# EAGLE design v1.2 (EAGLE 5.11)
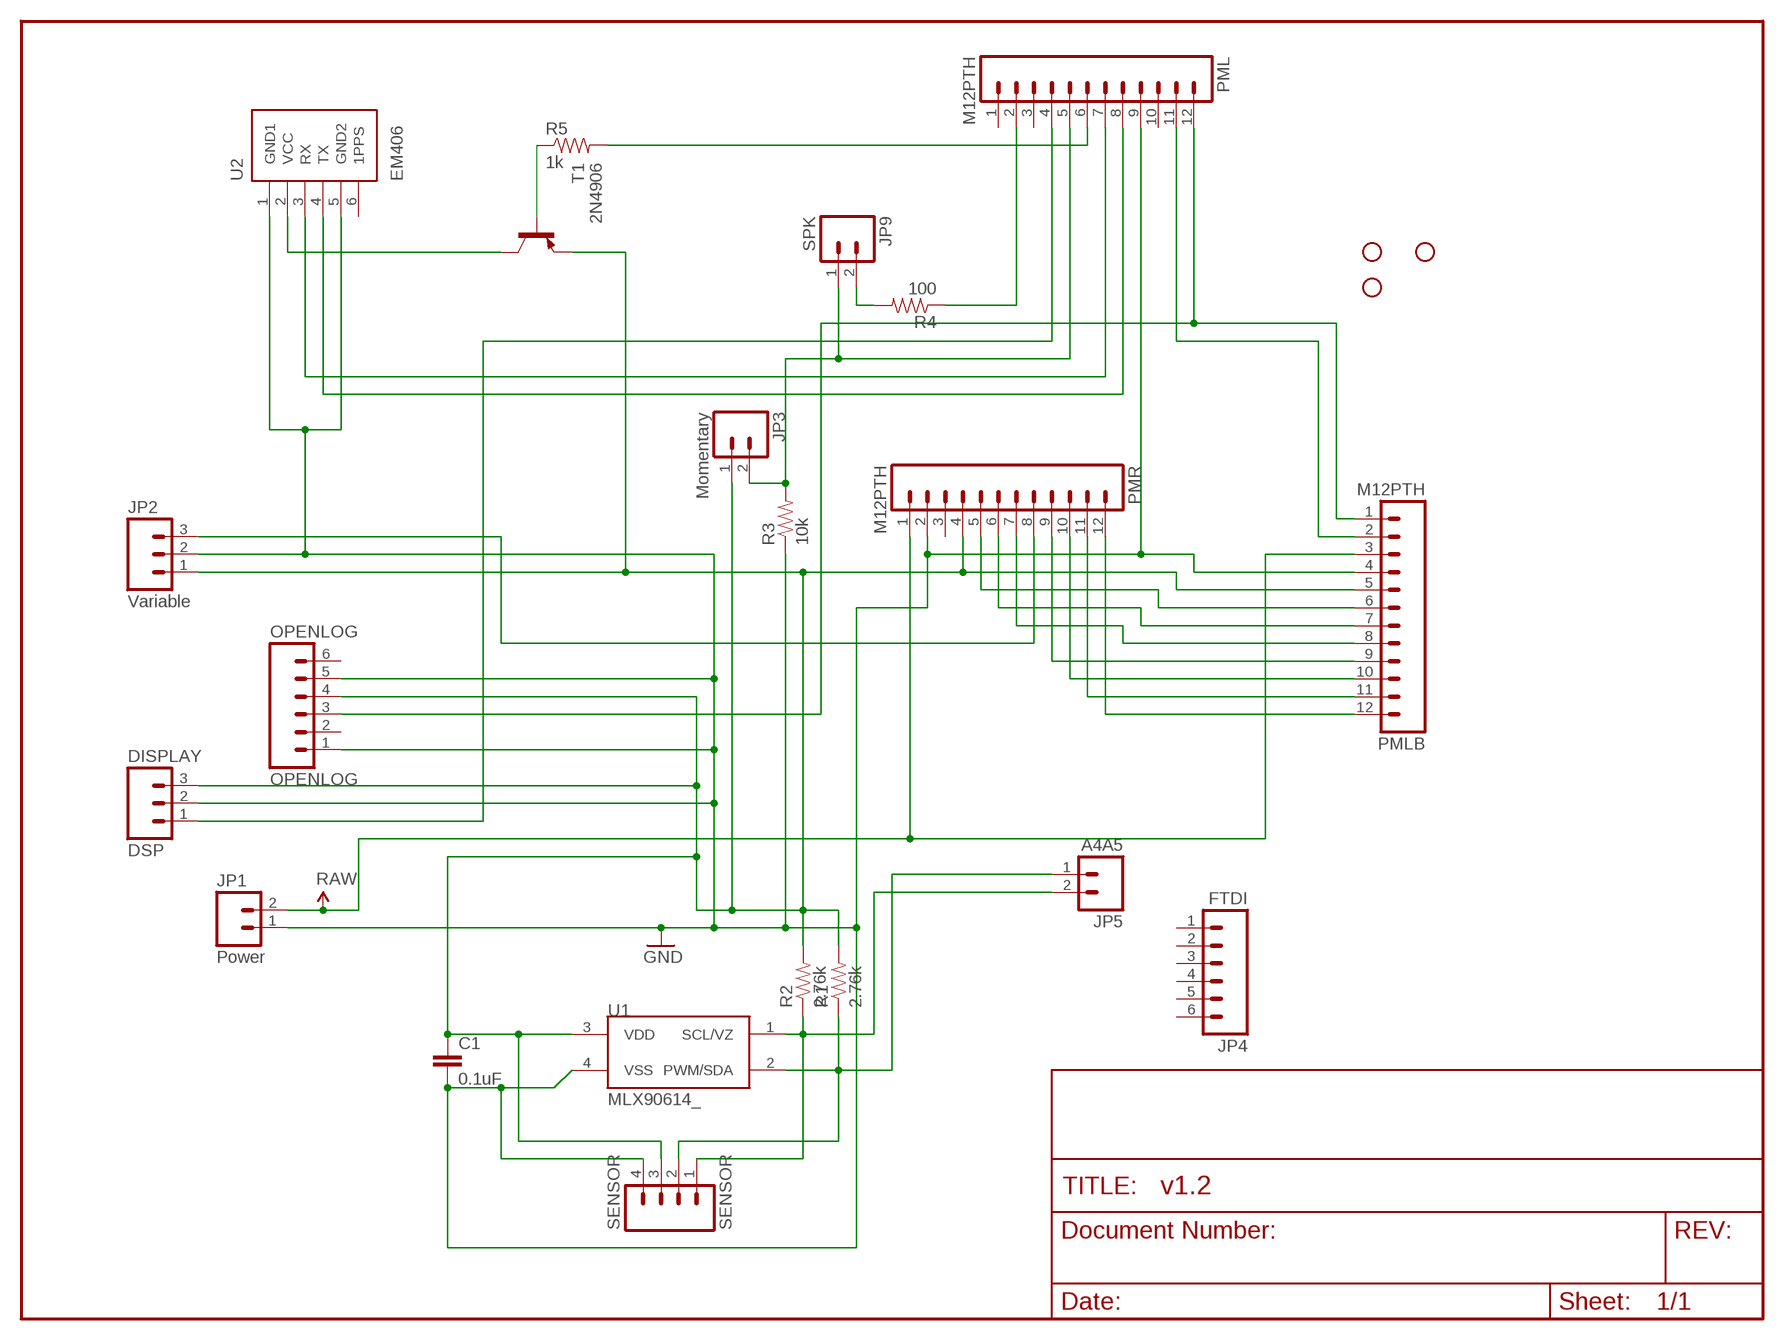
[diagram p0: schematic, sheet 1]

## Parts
2N4906  T1  2N3906-PNP-TO92-EBC  [TO92-EBC]
C1  0.1uF  CAPPTH3  [CAP-PTH-LARGE]
DISPLAY  DSP  M03SCREW_LOCK  [SCREWTERMINAL-3.5MM-3_LOCK.007S]
JP1  Power  M02JST-PTH-2  [JST-2-PTH]
JP2  Variable  M03SCREW_LOCK  [SCREWTERMINAL-3.5MM-3_LOCK.007S]
JP3  Momentary  M02JST-PTH-2  [JST-2-PTH]
JP4  FTDI  M06SIP  [1X06]
JP5  A4A5  M02PTH  [1X02]
JP6  STAND-OFFTIGHT  [STAND-OFF-TIGHT]
JP7  STAND-OFFTIGHT  [STAND-OFF-TIGHT]
JP8  STAND-OFFTIGHT  [STAND-OFF-TIGHT]
JP9  SPK  M023.5MM  [SCREWTERMINAL-3.5MM-2]
OPENLOG  OPENLOG  M06LOCK  [1X06_LOCK]
PML  M12PTH  [1X12]
PMLB  M12PTH  [1X12]
PMR  M12PTH  [1X12]
R1  2.76k  RESISTORPTH-1/4W  [AXIAL-0.4]
R2  2.76k  RESISTORPTH-1/4W  [AXIAL-0.4]
R3  10k  RESISTORPTH-1/4W  [AXIAL-0.4]
R4  100  RESISTORPTH-1/4W  [AXIAL-0.4]
R5  1k  RESISTORPTH-1/4W  [AXIAL-0.4]
SENSOR  SENSOR  M04SCREW_LOCK  [SCREWTERMINAL-3.5MM-4_LOCK]
U1  MLX90614_  [TO-39]
U2  EM406  [EM406]

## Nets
GND: C1.2 DISPLAY.2 JP1.1 JP2.2 OPENLOG.1 OPENLOG.5 PML.9 PMLB.4 PMR.2 R3.P$1 SENSOR.4 U1.4(VSS) U2.1(GND1) U2.5(GND2)
N$2: JP5.1 R1.P$1 SENSOR.2 U1.2(PWM/SDA)
N$3: JP3.2 JP9.1 PML.5 R3.P$2
N$4: DISPLAY.1 PML.4
N$5: JP2.3 PMR.8
N$6: OPENLOG.3 PML.12 PMLB.1
N$7: 2N4906.E C1.1 DISPLAY.3 JP2.1 JP3.1 OPENLOG.4 PMLB.5 PMR.4 R1.P$2 R2.P$2 SENSOR.3 U1.3(VDD)
N$8: PML.11 PMLB.2
N$9: PMLB.12 PMR.12
N$10: PMLB.11 PMR.11
N$11: PMLB.10 PMR.10
N$12: PMLB.9 PMR.9
N$13: PMLB.8 PMR.7
N$14: PMLB.7 PMR.6
N$15: PMLB.6 PMR.5
N$16: JP9.2 R4.P$2
N$17: PML.2 R4.P$1
N$18: 2N4906.B R5.P$1
N$19: 2N4906.C U2.2(VCC)
N$20: PML.8 U2.4(TX)
N$21: PML.7 U2.3(RX)
N$22: PML.6 R5.P$2
SENSOR: JP5.2 R2.P$1 SENSOR.1 U1.1(SCL/VZ)
VCC: JP1.2 PMLB.3 PMR.1 ; supply symbol labelled RAW
Unconnected: JP4.1 JP4.2 JP4.3 JP4.4 JP4.5 JP4.6 OPENLOG.2 OPENLOG.6 PML.1 PML.3 PML.10 PMR.3 U2.6(1PPS)

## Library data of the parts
2N4906 = transistor-neu-to92:*-PNP-: PNP Transistror
C1 = SparkFun:CAP: Capacitor
DISPLAY JP2 = SparkFun:M03: Header 3 Standard 3-pin 0.1" header. Use with straight break away headers (SKU : PRT-00116), right angle break away headers (PRT-00553), swiss pins (PRT-00743), machine pins (PRT-00117), and female headers (PRT-00115). Molex polarized connector foot print use with SKU : PRT-08232 with associated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
JP1 JP3 JP5 JP9 = SparkFun:M02: Header 2
JP4 OPENLOG = SparkFun:M06: Header 6 Standard 6-pin 0.1" header. Use with straight break away headers (SKU : PRT-00116), right angle break away headers (PRT-00553), swiss pins (PRT-00743), machine pins (PRT-00117), and female headers (PRT-00115). Molex polarized connector foot print use with SKU : PRT-08094 with associated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
JP6-JP8 = SparkFun:STAND-OFF: Stand Off
PML PMLB PMR = SparkFun:M12: Header 12 Standard 12-pin 0.1" header. Use with straight break away headers (SKU : PRT-00116), right angle break away headers (PRT-00553), swiss pins (PRT-00743), machine pins (PRT-00117), and female headers (PRT-00115).
R1-R5 = SparkFun:RESISTOR: Resistor
SENSOR = SparkFun:M04: Header 4 Standard 4-pin 0.1" header. Use with straight break away headers (SKU : PRT-00116), right angle break away headers (PRT-00553), swiss pins (PRT-00743), machine pins (PRT-00117), and female headers (PRT-00115). Molex polarized connector foot print use with SKU : PRT-08231 with associated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
U1 = SparkFun:MLX90614: Melexis IR Thermometer
U2 = SparkFun:EM406: EM406 Connector Proven layout and schematic for EM406 connector. Spark Fun Electronics SKU : GPS-00579

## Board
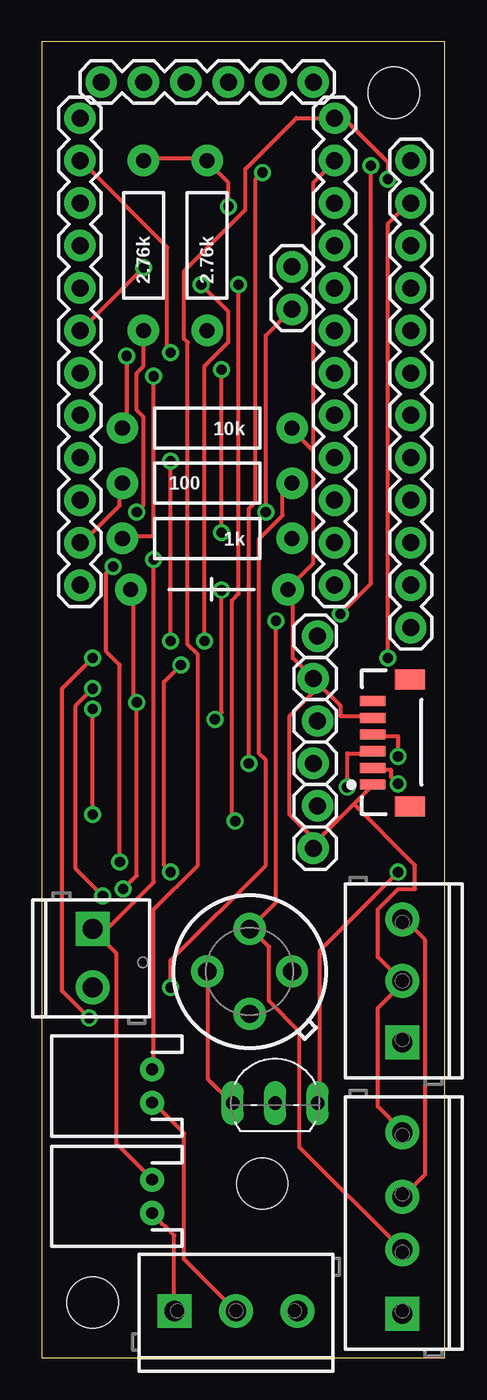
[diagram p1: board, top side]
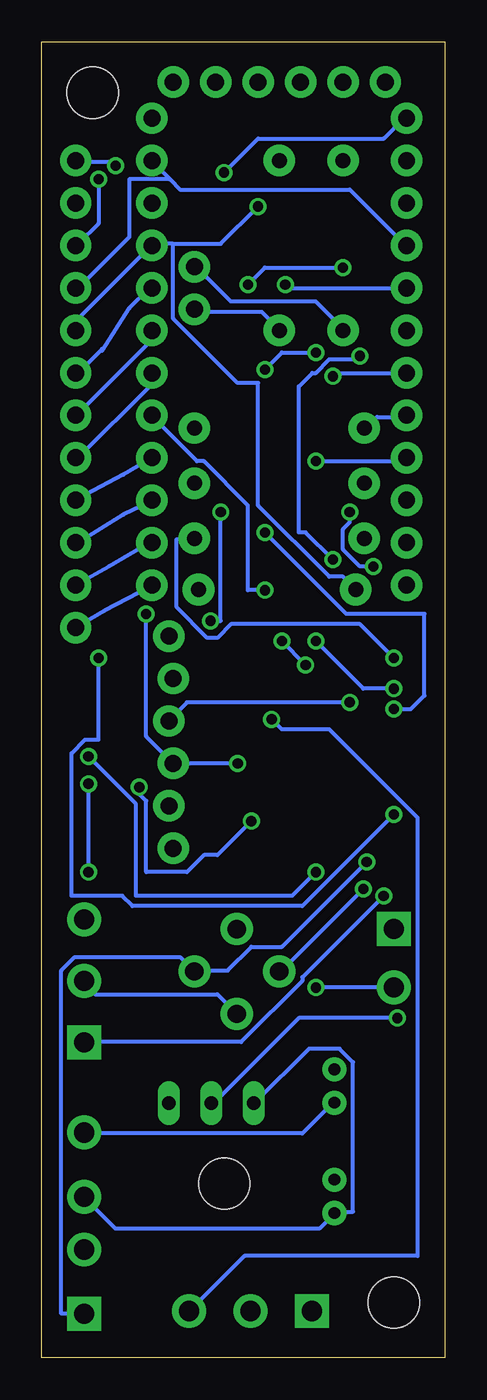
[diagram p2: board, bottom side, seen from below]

Size 24.13 x 78.74 mm. Coordinates in mm from the lower left corner, seen from the top.
Outline: 0,0 24.13,0 24.13,78.74 0,78.74 0,0
Copper layers (1*16): Top 0.035mm / dielectric 1.5mm / Bottom 0.035mm
Design rules "default": minimum track width 10mil, minimum drill 24mil, track to track 8mil, track to pad 8mil, pad to pad 8mil, via to via 8mil, smd to smd 8mil, copper to edge 40mil, drill to drill 8mil, minimum pad ring 10mil, minimum via ring 8mil, stop-mask expansion 4mil, vias tented up to drill 0mil, thermal gap 10mil

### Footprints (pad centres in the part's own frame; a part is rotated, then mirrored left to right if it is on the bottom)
TO92-EBC = drill 0.813 long: B 0,-1.27; C 2.54,-1.27; E -2.54,-1.27
CAP-PTH-LARGE = drill 0.9 pad 1.905 round: 1 -4.826,0; 2 4.572,0
SCREWTERMINAL-3.5MM-3_LOCK.007S = drill 1.2 pad 2.032 square: 1 -0.178,0 | drill 1.2 pad 2.032 round: 2 3.5,0; 3 7.178,0
JST-2-PTH = drill 0.7 pad 1.448 round: 1 -1,0; 2 1,0
1X06 = drill 1.016 pad 1.88 round: 1 0,0; 2 2.54,0; 3 5.08,0; 4 7.62,0; 5 10.16,0; 6 12.7,0
1X02 = drill 1.016 pad 1.88 round: 1 0,0; 2 2.54,0
STAND-OFF-TIGHT = hole 3.048: 0,0
SCREWTERMINAL-3.5MM-2 = drill 1.2 pad 2.032 square: 1 0,0 | drill 1.2 pad 2.032 round: 2 3.5,0
1X06_LOCK = drill 1.016 pad 1.88 round: 1 0,0; 2 2.54,-0.254; 3 5.08,0; 4 7.62,-0.254; 5 10.16,0; 6 12.7,-0.254
1X12 = drill 1.016 pad 1.88 round: 1 0,0; 2 2.54,0; 3 5.08,0; 4 7.62,0; 5 10.16,0; 6 12.7,0; 7 15.24,0; 8 17.78,0; 9 20.32,0; 10 22.86,0; 11 25.4,0; 12 27.94,0
AXIAL-0.4 = drill 0.9 pad 1.88 round: P$1 -5.08,0; P$2 5.08,0
SCREWTERMINAL-3.5MM-4_LOCK = drill 1.2 pad 2.032 square: 1 -0.178,0 | drill 1.2 pad 2.032 round: 2 3.678,0; 3 6.822,0; 4 10.678,0
TO-39 = drill 1.1 pad 1.93 round: 1 2.54,0; 2 0,2.54; 3 -2.54,0; 4 0,-2.54
EM406 = smd 0.6 x 1.55: 1 0,0; 2 1,0; 3 2,0; 4 3,0; 5 4,0; 6 5,0 | smd 1.2 x 1.8: P$1 -1.3,-2.225; P$2 6.3,-2.225

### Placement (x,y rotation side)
2N4906  13.97,16.51 0 top
C1  10.16,45.97 0 top
DISPLAY  21.59,19.05 90 top
JP1  6.6,16.26 90 top
JP2  8.13,2.79 0 top
JP3  6.6,9.65 90 top
JP4  16.26,76.33 180 top
JP5  14.99,62.74 90 top
JP6  3.05,3.3 0 top
JP7  21.08,75.69 0 top
JP8  13.21,10.41 0 top
JP9  3.05,25.65 270 top
OPENLOG  16.26,30.48 90 top
PML  2.29,46.23 90 top
PMLB  22.1,71.63 270 top
PMR  17.53,74.17 270 top
R1  9.91,66.55 90 top
R2  6.1,66.55 90 top
R3  9.91,55.63 180 top
R4  9.91,52.32 0 top
R5  9.91,49.02 180 top
SENSOR  21.59,2.79 90 top
U1  12.45,23.11 0 top
U2  19.81,34.29 90 top

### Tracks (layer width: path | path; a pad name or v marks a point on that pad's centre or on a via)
GND
  Top 0.254: JP2.2 11.58,2.85 8.53,5.89 8.53,13.41 6.71,15.24 JP1.1 | SENSOR.4 21.54,13.61 20.12,15.04 20.12,20.93 21.54,22.35 DISPLAY.2 21.54,22.55 20.12,23.98 20.12,26.82 21.34,28.04 22.35,28.04 22.35,29.46 18.69,33.12 | 16.46,30.89 16.26,30.68 OPENLOG.1 16.46,30.89 | 18.69,33.12 16.46,30.89 | 18.69,33.12 19.71,34.14 U2.1 | 16.66,40.23 17.88,39.01 17.88,38.41 19.71,38.41 U2.5 | 16.26,54.25 15.04,55.47 R3.P$1 | 16.26,54.25 16.26,47.55 15.04,46.33 | 15.04,46.33 14.83,46.13 C1.2 15.04,46.33 | 15.04,46.33 15.04,41.86 OPENLOG.5 16.66,40.23 | 16.46,30.89 14.83,32.51 14.83,38.41 16.66,40.23 | 16.26,54.25 16.26,70.31 17.48,71.53 PMR.2
  Bottom 0.254: U1.4 13.61,21.74 20.93,21.74 21.54,22.35 DISPLAY.2 | JP1.1 6.71,15.24 8.53,13.41 21.54,13.41 SENSOR.4 | 16.46,70.51 17.48,71.53 PMR.2 | 16.46,70.51 15.85,69.9 5.69,69.9 2.44,66.65 PML.9 | 16.46,70.51 18.9,70.51 18.9,67.06 21.95,64.01 PMLB.4
N$2  (via drill 0.61)
  Top 0.254: SENSOR.2 21.54,6.5 15.44,12.6 15.44,19.51 13.61,21.34 13.61,24.59 12.6,25.6 U1.2 14.02,27.23 v14.02,44.09 | v13.41,50.6 13.41,61.16 JP5.1
  Bottom 0.254: R1.P$1 9.96,61.57 10.97,62.59 14.83,62.59 JP5.1 | v13.41,50.6 13.41,44.09 v14.02,44.09
N$3  (via drill 0.61)
  Top 0.254: 3.45,25.2 3.05,25.6 JP9.1 3.45,25.2 | 3.45,25.2 4.47,24.18 4.47,12.8 6.5,10.77 JP3.2 | v5.08,59.94 5.08,55.88 R3.P$2 | v6.71,47.75 6.71,28.45 3.45,25.2
  Bottom 0.254: R3.P$2 4.67,55.68 4.06,56.29 2.44,56.29 PML.5 | v5.08,59.94 5.28,59.74 6.91,59.74 7.72,58.93 7.92,58.93 8.74,58.12 8.74,49.38 8.33,49.38 v6.71,47.75
N$4  (via drill 0.61)
  Top 0.254: v7.72,42.88 v7.72,53.65 | v3.05,40.03 2.03,39.01 2.03,29.26 v3.66,27.64
  Bottom 0.254: v7.72,53.65 2.64,53.65 2.44,53.85 PML.4 | v7.72,42.88 4.88,40.03 v3.05,40.03 | v3.66,27.64 8.53,22.76 8.53,22.55 12.19,18.9 21.54,18.9 DISPLAY.1
N$5  (via drill 0.61)
  Top 0.254: v10.77,45.92 10.77,38.61 v10.36,38.2
  Bottom 0.254: v10.77,45.92 11.79,45.92 11.79,51 14.43,53.65 14.83,53.65 17.48,56.29 PMR.8 | v10.36,38.2 9.75,37.59 6.91,37.59 1.63,32.31 1.63,6.1 11.99,6.1 15.24,2.85 JP2.3
N$6  (via drill 0.61)
  Top 0.254: v17.88,44.5 19.71,46.33 v19.71,71.32 | v13.21,70.92 12.8,70.51 12.8,51.21 12.39,50.8 v12.39,35.56
  Bottom 0.254: v17.88,44.5 17.88,37.19 OPENLOG.3 v12.39,35.56 | v19.71,71.32 19.91,71.53 21.95,71.53 PMLB.1 | v13.21,70.92 11.18,72.95 3.66,72.95 2.44,74.17 PML.12
N$7  (via drill 0.61)
  Top 0.254: 2N4906.E 11.38,15.24 9.96,16.66 9.96,22.96 U1.3 | JP3.1 6.71,8.53 7.92,7.32 7.92,2.85 JP2.1 | DISPLAY.3 21.74,26.21 22.96,24.99 22.96,10.97 21.74,9.75 SENSOR.3 | C1.1 5.49,45.92 5.49,39.42 v5.69,39.22 5.69,28.85 v4.88,28.04 | R2.P$2 6.1,71.73 9.75,71.73 R1.P$2 9.96,71.53 11.18,70.31 v11.18,68.89
  Bottom 0.254: SENSOR.3 21.54,9.55 19.71,7.72 7.52,7.72 6.71,8.53 JP3.1 6.5,8.74 5.49,8.74 5.49,17.68 6.3,18.49 8.13,18.49 11.38,15.24 2N4906.E | v5.69,39.22 15.44,39.22 16.46,38.2 OPENLOG.4 | PMLB.5 21.95,61.57 21.95,62.18 17.68,66.45 PMR.4 17.48,66.65 16.26,66.65 | v11.18,68.89 13.41,66.65 16.26,66.65 | 16.26,66.65 16.26,62.18 12.39,58.32 11.18,58.32 11.18,51 6.91,46.74 6.1,46.74 C1.1 | v4.88,28.04 9.75,23.16 U1.3
N$8  (via drill 0.61)
  Top 0.254: v20.73,41.86 20.73,67.87 21.95,69.09 PMLB.2 | v3.05,32.51 v3.05,38.81 | v10.77,49.38 v10.77,59.13 | v7.72,60.15 7.52,60.35 7.52,66.45 2.44,71.53 PML.11
  Bottom 0.254: v20.73,41.86 20.73,36.98 21.54,36.98 22.35,36.17 22.35,27.64 19.3,27.64 18.69,27.03 8.53,27.03 v3.05,32.51 | v3.05,38.81 2.03,38.81 1.22,39.62 1.22,44.5 5.89,44.5 v10.77,49.38 | v10.77,59.13 9.75,60.15 v7.72,60.15
N$9
  Bottom 0.254: PMR.12 17.68,46.13 20.37,44.7 PMLB.12
N$10
  Bottom 0.254: PMR.11 17.68,48.77 20.12,47.35 21.95,46.33 PMLB.11
N$11
  Bottom 0.254: PMLB.10 21.95,48.77 19.25,50.44 17.68,51.21 PMR.10
N$12
  Bottom 0.254: PMLB.9 21.95,51.41 19.25,52.83 PMR.9
N$13
  Bottom 0.254: PMLB.8 21.95,53.85 17.68,58.12 17.68,58.93 PMR.7
N$14
  Bottom 0.254: PMLB.7 21.95,56.49 17.68,60.76 17.68,61.37 PMR.6
N$15
  Bottom 0.254: PMLB.6 21.95,58.93 20.52,60.35 20.52,60.25 18.9,62.79 17.68,64.01 PMR.5
N$16  (via drill 0.61)
  Top 0.254: v7.72,22.15 7.72,23.77 13.41,29.46 13.41,35.76 13.01,36.17 13.01,48.97 14.43,50.39 14.43,51.82 14.83,52.22 R4.P$2
  Bottom 0.254: v7.72,22.15 JP9.2
N$17
  Top 0.254: PML.2 2.44,48.77 4.67,51 4.67,52.22 R4.P$1
N$18  (via drill 0.61)
  Top 0.254: v2.85,20.32 1.22,21.95 1.22,40.03 v3.05,41.86
  Bottom 0.254: v2.85,20.32 8.74,20.32 13.82,15.24 2N4906.B | v3.05,41.86 5.08,43.89 12.8,43.89 13.61,43.08 14.22,43.08 16.05,44.91 16.05,48.97 15.04,48.97 R5.P$1
N$19  (via drill 0.61)
  Top 0.254: v21.34,34.34 20.93,34.75 20.93,35.15 19.91,35.15 U2.2 | v21.34,29.06 16.66,24.38 16.66,15.24 2N4906.C
  Bottom 0.254: v21.34,29.06 v21.34,34.34
N$20  (via drill 0.61)
  Top 0.254: v21.34,35.97 21.34,37.19 19.91,37.19 U2.4 | v7.72,29.06 7.32,29.46 7.32,40.44 v8.33,41.45 | v9.75,42.88 9.75,59.33 11.18,60.76 11.18,62.59 v9.55,64.21
  Bottom 0.254: v21.34,35.97 18.49,33.12 18.49,27.64 9.14,27.64 v7.72,29.06 | v8.33,41.45 v9.75,42.88 | v9.55,64.21 9.35,64.01 PML.8
N$21  (via drill 0.61)
  Top 0.254: v18.29,34.14 18.29,36.17 19.71,36.17 U2.3 | v11.58,32.11 11.38,32.31 11.38,45.31 11.79,45.72 v11.79,64.21 | v6.1,65.23 2.44,61.57 PML.7
  Bottom 0.254: v18.29,34.14 18.29,33.73 17.88,33.33 17.88,29.06 15.44,29.06 14.43,30.07 13.61,30.07 v11.58,32.11 | v11.79,64.21 10.77,65.23 v6.1,65.23
N$22  (via drill 0.61)
  Top 0.254: v6.71,58.73 6.71,49.17 4.88,49.17 R5.P$2
  Bottom 0.254: v6.71,58.73 6.5,58.93 PML.6
SENSOR  (via drill 0.61)
  Top 0.254: v5.69,50.6 6.1,51 6.1,56.29 5.69,56.69 5.69,58.93 6.1,59.33 R2.P$1 | v4.27,47.35 3.86,46.94 3.86,42.27 4.67,41.45 v4.67,29.67
  Bottom 0.254: R2.P$1 6.1,61.57 7.72,63.2 12.8,63.2 14.83,65.23 JP5.2 | SENSOR.1 21.74,2.64 22.96,2.64 22.96,23.16 22.15,23.98 15.85,23.98 U1.1 14.83,23.16 13.01,23.16 11.58,24.59 9.75,24.59 v4.67,29.67 | v5.69,50.6 5.69,49.99 6.1,49.58 6.1,48.36 5.08,47.35 v4.27,47.35
VCC  (via drill 0.61)
  Top 0.254: JP1.2 6.71,17.27 6.71,26.82 9.35,29.46 9.35,42.06 8.74,42.67 8.74,60.76 8.53,60.96 8.53,65.02 12.19,68.68 12.19,71.12 15.24,74.17 PMR.1 18.09,74.17 20.73,71.53 v20.73,70.51
  Bottom 0.254: v20.73,70.51 20.73,67.87 21.95,66.65 PMLB.3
